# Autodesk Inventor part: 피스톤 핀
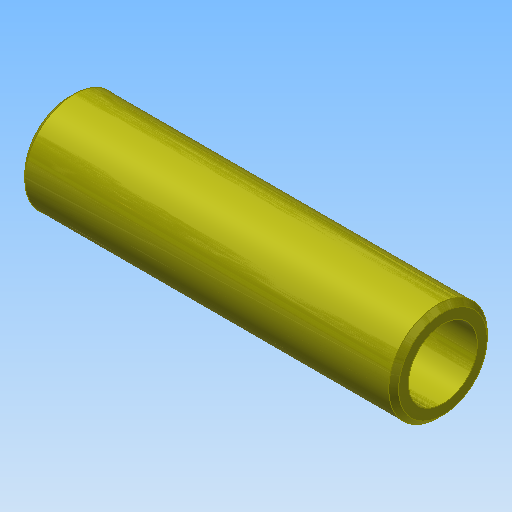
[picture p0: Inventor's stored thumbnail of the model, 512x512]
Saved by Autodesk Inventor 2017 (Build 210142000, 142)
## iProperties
Created: 2017-05
Part Number: 피스톤 핀
Material: 알루미늄 6061
Document SubType Name: Modeling
Designer: mduedu
Density: 2.71 g/cm^3
Mass: 4.10432 g
Surface Area: 20.9053 cm^2
Volume: 1.51451 cm^3
Appearance: 노란색
Author: mduedu
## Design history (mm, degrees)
sketch "스케치1"
  geometry: C1 r 5 at (0, 0); C2 r 3.5 at (0, 0); 1 further point
  constraints: 2 centre point, 2 coincident
  dimensions: "d0" = 10 diameter of C1; "d1" = 7 diameter of C2
extrude "돌출1" new body sketch "스케치1" stored distance "d2" = 38; taper "d3" = 0 deg
chamfer "모따기1" distance "d4" = 0.5; stored, may be unused: second distance "d5" = 2, angle "d6" = 45 deg
node "솔리드1"
